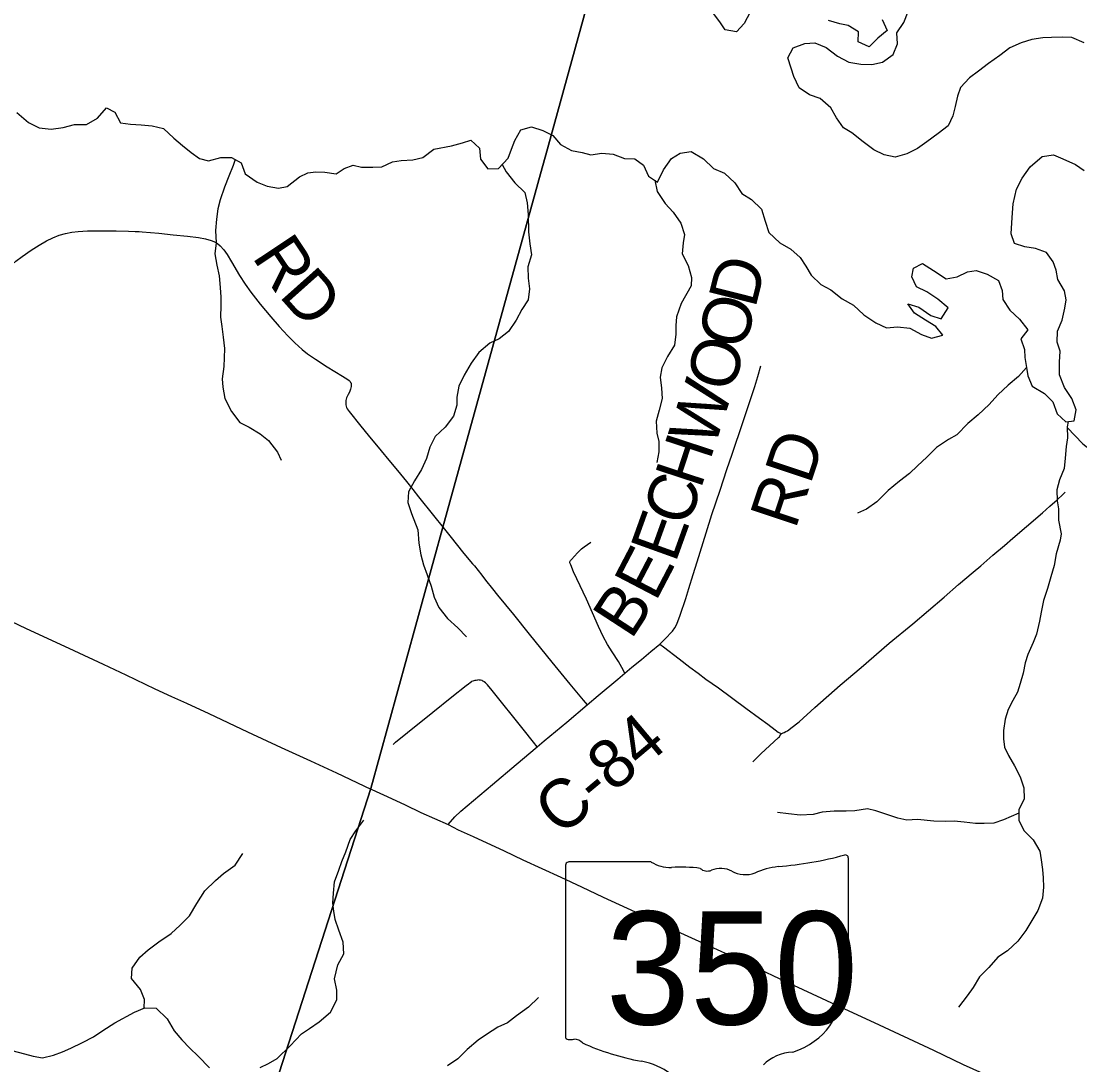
# Model space of a CAD drawing. Extents: x 0 to 34, y 0 to 22.
# Drawn here: x 3.583 to 4.817, y 17.368 to 18.585 of the extents above; entities that cross this region are included whole.
import ezdxf

# ---------------------------------------------------------------- set-up
doc = ezdxf.new("R2010")
doc.units = 0
for name, color, linetype in [('GM_X_County_Road', 7, 'Continuous'), ('GM_X_County_Road_Text', 7, 'Continuous'), ('GM_X_Major_Lake', 7, 'Continuous'), ('GM_X_Minor_River', 7, 'Continuous'), ('GM_X_State_Location', 7, 'Continuous'), ('GM_X_State_Route', 7, 'Continuous'), ('GM_X_State_Shield', 7, 'Continuous'), ('GM_X_Township_Road', 7, 'Continuous'), ('GM_X_Township_Road_Text', 7, 'Continuous')]:
    doc.layers.add(name, color=color, linetype=linetype)

msp = doc.modelspace()

# ---------------------------------------------------------------- linework, layer by layer
at = {"layer": 'GM_X_County_Road'}
for points in [[(4.3273, 17.8584), (4.3332, 17.8639), (4.342, 17.8734), (4.3449, 17.8773), (4.3471, 17.8816), (4.351, 17.892), (4.3575, 17.9114), (4.3611, 17.9233), (4.3661, 17.9393), (4.3709, 17.9541), (4.3813, 17.9879), (4.3881, 18.0093), (4.3975, 18.0376), (4.4054, 18.0619), (4.4118, 18.0799), (4.4241, 18.1166), (4.4381, 18.1587), (4.4417, 18.1703), (4.4451, 18.1829)], [(4.2866, 17.8244), (4.2949, 17.8314), (4.3059, 17.8405), (4.3168, 17.8498), (4.3273, 17.8584)], [(4.2427, 17.7876), (4.2554, 17.7982), (4.2783, 17.8174), (4.2866, 17.8244)], [(4.1843, 17.7384), (4.1926, 17.7454), (4.2188, 17.7674), (4.2427, 17.7876)], [(4.0806, 17.6479), (4.0883, 17.6569), (4.0952, 17.6633), (4.1323, 17.6946), (4.1597, 17.7179), (4.1843, 17.7384)]]:
    msp.add_lwpolyline(points, dxfattribs=at)
at = {"layer": 'GM_X_Major_Lake'}
for points in [[(4.4326, 18.5952), (4.4258, 18.5821), (4.4168, 18.5721), (4.4036, 18.5744), (4.3971, 18.584), (4.3898, 18.5937)], [(4.8218, 18.5594), (4.8075, 18.5658), (4.7962, 18.5661), (4.784, 18.5657), (4.7738, 18.5652), (4.7609, 18.5633), (4.7486, 18.5595), (4.7352, 18.5534), (4.7236, 18.5446), (4.7105, 18.5355), (4.6988, 18.5264), (4.6884, 18.5187), (4.6778, 18.5072), (4.6745, 18.4971), (4.6715, 18.485), (4.6689, 18.4744), (4.6633, 18.4628), (4.6517, 18.4537), (4.6385, 18.4438), (4.6277, 18.4361), (4.6154, 18.43), (4.6016, 18.4262), (4.5888, 18.4289), (4.5769, 18.4345), (4.5643, 18.444), (4.5513, 18.4546), (4.5416, 18.4601), (4.5332, 18.4718), (4.5268, 18.4837), (4.5142, 18.4943), (4.5018, 18.4988), (4.4896, 18.5071), (4.4835, 18.5202), (4.4804, 18.5298), (4.4765, 18.542), (4.4829, 18.5536), (4.4963, 18.5585), (4.5081, 18.5593), (4.5212, 18.554), (4.5345, 18.5438), (4.5476, 18.537), (4.5616, 18.5347), (4.5744, 18.534), (4.587, 18.537), (4.5994, 18.5458), (4.6043, 18.5582), (4.6035, 18.5711), (4.6118, 18.583), (4.6167, 18.5958)], [(4.5865, 18.5867), (4.5922, 18.5737), (4.5814, 18.5649), (4.5712, 18.5549), (4.5585, 18.5606), (4.5588, 18.5723), (4.5469, 18.5795), (4.5371, 18.5817), (4.524, 18.5854)], [(3.5777, 18.4781), (3.5914, 18.4664), (3.6037, 18.4603), (3.6177, 18.4588), (3.6317, 18.4607), (3.6451, 18.4641), (3.6591, 18.4641), (3.6718, 18.4714), (3.6824, 18.4836), (3.6921, 18.4784), (3.6986, 18.4661), (3.7103, 18.4646)], [(3.7103, 18.4646), (3.7227, 18.4639), (3.7356, 18.4628), (3.7487, 18.4594), (3.7609, 18.4484), (3.7709, 18.4398), (3.7809, 18.4315), (3.7906, 18.4244), (3.8011, 18.4219), (3.8156, 18.4256), (3.8281, 18.4257), (3.8393, 18.4193), (3.8438, 18.4066), (3.8579, 18.3968), (3.8696, 18.3923), (3.8828, 18.39), (3.893, 18.392), (3.9074, 18.403), (3.917, 18.4077), (3.9265, 18.4089), (3.9367, 18.4086), (3.9499, 18.4067), (3.9595, 18.4129), (3.9699, 18.4168), (3.9797, 18.4146), (3.9929, 18.4143), (4.0032, 18.4147), (4.0158, 18.4205), (4.0257, 18.4221), (4.0394, 18.4228), (4.0512, 18.4256), (4.064, 18.4354), (4.0846, 18.4394), (4.0972, 18.4429), (4.1071, 18.446), (4.1171, 18.4366), (4.1182, 18.4237), (4.127, 18.4125), (4.1391, 18.4129), (4.1504, 18.4251), (4.1545, 18.4356), (4.1582, 18.4454), (4.1654, 18.4581), (4.1776, 18.4615), (4.1908, 18.4573), (4.2027, 18.4513), (4.2115, 18.4408), (4.2242, 18.4337), (4.237, 18.4314), (4.2468, 18.4289), (4.2597, 18.4308), (4.2729, 18.4297), (4.286, 18.4247), (4.2981, 18.424), (4.3085, 18.4169), (4.3142, 18.4039), (4.3246, 18.3971), (4.3315, 18.4113), (4.341, 18.4247), (4.351, 18.4309), (4.3639, 18.4328), (4.3781, 18.4241), (4.3899, 18.4128), (4.4026, 18.4075), (4.4148, 18.3961), (4.4228, 18.3838), (4.4343, 18.3766), (4.4457, 18.3653), (4.4502, 18.3515), (4.4544, 18.3381), (4.4673, 18.326), (4.48, 18.3188), (4.4911, 18.309), (4.4976, 18.299), (4.5037, 18.2886), (4.5152, 18.2776), (4.5267, 18.2713), (4.5397, 18.261), (4.5531, 18.2534), (4.5653, 18.2421), (4.579, 18.233), (4.5914, 18.227), (4.6043, 18.2281), (4.6186, 18.2266), (4.6324, 18.2194), (4.6441, 18.2149), (4.6571, 18.2187), (4.649, 18.2288), (4.6371, 18.2359), (4.6244, 18.2443), (4.6164, 18.2551), (4.6292, 18.2513), (4.6433, 18.2415), (4.6553, 18.2377), (4.6636, 18.2504), (4.6514, 18.2606), (4.6384, 18.2689), (4.6265, 18.2749), (4.6211, 18.2865), (4.6229, 18.2967), (4.6337, 18.302)], [(4.6337, 18.302), (4.6463, 18.2941), (4.6612, 18.2842), (4.6741, 18.2865), (4.6861, 18.2923), (4.696, 18.2939), (4.7091, 18.2897), (4.7221, 18.2821), (4.7263, 18.2707), (4.7272, 18.26), (4.7352, 18.2476), (4.7466, 18.2371), (4.7565, 18.2247), (4.7482, 18.2143), (4.7524, 18.202), (4.7529, 18.1925), (4.7548, 18.1807), (4.7565, 18.1712), (4.7614, 18.1589), (4.7759, 18.1505), (4.7855, 18.1408), (4.7904, 18.1266), (4.8008, 18.1176), (4.8102, 18.1185), (4.8125, 18.1313), (4.8076, 18.1447), (4.7992, 18.1575), (4.7932, 18.1724), (4.7933, 18.1869), (4.794, 18.1997), (4.7905, 18.2104), (4.7909, 18.2233), (4.7962, 18.2361), (4.7996, 18.25), (4.801, 18.2599), (4.7991, 18.2702), (4.7911, 18.2833), (4.7892, 18.2943), (4.786, 18.3039), (4.778, 18.3151), (4.7653, 18.3197), (4.7528, 18.3215), (4.7408, 18.3253), (4.737, 18.3367), (4.7377, 18.3496), (4.7384, 18.361), (4.7391, 18.3716), (4.743, 18.3886), (4.7498, 18.4016), (4.7589, 18.4147), (4.7729, 18.4268), (4.7862, 18.4287), (4.797, 18.4242), (4.812, 18.4174), (4.822, 18.4106)]]:
    msp.add_lwpolyline(points, dxfattribs=at)
at = {"layer": 'GM_X_Minor_River'}
for points in [[(3.8323, 18.4232), (3.83, 18.4163), (3.8248, 18.4039), (3.82, 18.3911), (3.8148, 18.3764), (3.8123, 18.3658), (3.8105, 18.3537), (3.8095, 18.3405), (3.81, 18.326), (3.8086, 18.3135), (3.811, 18.3002), (3.8137, 18.2876), (3.815, 18.2743), (3.8155, 18.2629), (3.8157, 18.2531), (3.8154, 18.2394), (3.8167, 18.2288), (3.8183, 18.2162), (3.82, 18.2029), (3.8197, 18.1919), (3.8191, 18.1821), (3.8173, 18.1677), (3.8179, 18.1578), (3.8203, 18.1445), (3.8279, 18.1295), (3.8379, 18.1168), (3.8488, 18.1113), (3.8615, 18.1034), (3.8712, 18.0957), (3.8815, 18.0822), (3.8858, 18.0726)], [(4.1436, 18.4177), (4.1481, 18.4089), (4.1584, 18.3961), (4.17, 18.3849), (4.1727, 18.3727), (4.174, 18.3594), (4.1743, 18.3389), (4.1759, 18.3252), (4.1776, 18.3123), (4.1735, 18.2983), (4.174, 18.2851), (4.1756, 18.2725), (4.1738, 18.2596), (4.1664, 18.2484), (4.1597, 18.236), (4.1511, 18.2229), (4.1399, 18.2144), (4.1292, 18.2093), (4.1165, 18.1982), (4.1075, 18.1858), (4.0993, 18.172), (4.093, 18.1592), (4.0908, 18.1463), (4.0906, 18.1368), (4.0869, 18.124), (4.0772, 18.1113), (4.0656, 18.1005), (4.0593, 18.0878), (4.0552, 18.0746), (4.0497, 18.0618), (4.0414, 18.0487), (4.0344, 18.0359), (4.0337, 18.0234), (4.038, 18.0104), (4.0451, 17.9914)], [(4.3215, 18.3992), (4.3242, 18.386), (4.3337, 18.3722), (4.343, 18.3618), (4.3518, 18.3491), (4.3561, 18.3361), (4.3544, 18.3262), (4.3534, 18.3134), (4.3603, 18.2996), (4.3642, 18.2858), (4.364, 18.276), (4.3522, 18.2553), (4.3469, 18.2399), (4.346, 18.2297), (4.3461, 18.2198), (4.3444, 18.2069), (4.3361, 18.1938), (4.3298, 18.1803), (4.3277, 18.1697), (4.3293, 18.1568), (4.3302, 18.1446), (4.3265, 18.131), (4.3232, 18.1182), (4.3237, 18.1042), (4.3261, 18.0946), (4.3263, 18.0825), (4.3237, 18.07)], [(4.7548, 18.1809), (4.7456, 18.1705), (4.7332, 18.1602), (4.7213, 18.149), (4.7112, 18.1375), (4.6984, 18.1256), (4.6865, 18.1156), (4.6737, 18.1022), (4.6637, 18.0967), (4.6499, 18.0874), (4.6387, 18.0763), (4.6279, 18.0663), (4.6182, 18.0573), (4.6067, 18.0481), (4.5936, 18.0373), (4.5804, 18.0243), (4.5681, 18.0158), (4.5578, 18.0111)], [(4.8033, 18.1178), (4.8023, 18.1117), (4.8024, 18.0988), (4.8011, 18.0886), (4.7997, 18.075), (4.7987, 18.0629), (4.7931, 18.0497), (4.7902, 18.038), (4.7907, 18.0255), (4.792, 18.016), (4.7921, 18.0027), (4.795, 17.9869), (4.7941, 17.9795)], [(4.8023, 18.111), (4.8205, 18.092), (4.8324, 18.0823), (4.8433, 18.0768), (4.8534, 18.0724), (4.8654, 18.0669), (4.8759, 18.0602), (4.8806, 18.0476), (4.8804, 18.0377), (4.8809, 18.0256), (4.8924, 18.017), (4.8949, 18.0056), (4.8969, 17.9926), (4.9154, 17.9775)], [(4.0451, 17.9914), (4.0463, 17.9758), (4.0488, 17.9625), (4.052, 17.9507), (4.056, 17.9389), (4.0608, 17.9259), (4.0644, 17.9129), (4.0699, 17.9011), (4.0799, 17.8881), (4.0919, 17.8773), (4.102, 17.8669)], [(4.7941, 17.9795), (4.7893, 17.9634), (4.7869, 17.9498), (4.7833, 17.9366), (4.7793, 17.9233), (4.7745, 17.9093), (4.7717, 17.8957), (4.77, 17.8851), (4.7664, 17.87), (4.7624, 17.8602), (4.7565, 17.8462), (4.7534, 17.8364), (4.7509, 17.8242), (4.7473, 17.8125), (4.7441, 17.8023), (4.7387, 17.7925), (4.7332, 17.782), (4.73, 17.7706), (4.7279, 17.7574), (4.7278, 17.7479), (4.7292, 17.738), (4.7336, 17.7284), (4.7406, 17.7162), (4.7473, 17.7036), (4.7516, 17.6906), (4.7522, 17.6777), (4.7459, 17.6649), (4.7458, 17.6527), (4.752, 17.6405), (4.7625, 17.6301), (4.7703, 17.6167), (4.772, 17.6068), (4.7734, 17.5954), (4.774, 17.5859), (4.7746, 17.5749), (4.7736, 17.562), (4.7681, 17.5476), (4.7623, 17.5378), (4.7541, 17.5243), (4.7448, 17.5119), (4.7325, 17.5007), (4.7214, 17.4932), (4.7107, 17.4812), (4.6999, 17.4704), (4.6925, 17.4579), (4.6855, 17.4482), (4.6755, 17.435)], [(4.7459, 17.6611), (4.7279, 17.6533), (4.7165, 17.6493), (4.7055, 17.6491), (4.6953, 17.6492), (4.682, 17.6506), (4.6703, 17.6519), (4.6608, 17.6516), (4.6468, 17.6518), (4.6278, 17.6536), (4.6153, 17.653), (4.6047, 17.6554), (4.5919, 17.6594), (4.5791, 17.6637), (4.5693, 17.6661), (4.5548, 17.6637), (4.5446, 17.6634), (4.5305, 17.6636), (4.5165, 17.6623), (4.5062, 17.6594), (4.491, 17.6589), (4.4774, 17.6602), (4.4645, 17.6619)], [(3.8615, 17.3645), (3.8711, 17.3693), (3.8814, 17.3752), (3.8964, 17.3898), (3.9095, 17.4037), (3.919, 17.41), (3.9302, 17.4178), (3.9436, 17.429), (3.951, 17.4434), (3.9508, 17.4548), (3.948, 17.4681), (3.952, 17.4844), (3.959, 17.4972), (3.9581, 17.5108), (3.9533, 17.5246), (3.949, 17.5372), (3.9472, 17.5467), (3.9462, 17.5562), (3.9468, 17.5679), (3.9481, 17.5812), (3.9532, 17.5948), (3.9568, 17.6046), (3.9615, 17.616), (3.9662, 17.6303), (3.9728, 17.6405), (3.9825, 17.6529)], [(3.7262, 17.4339), (3.7265, 17.4438), (3.7218, 17.4556), (3.7114, 17.4683), (3.7123, 17.4804), (3.7212, 17.4932), (3.7308, 17.5018), (3.7434, 17.5111), (3.7576, 17.5208), (3.7684, 17.5305), (3.7792, 17.5414), (3.7877, 17.5557), (3.797, 17.5707), (3.8093, 17.5827), (3.8189, 17.5909), (3.8323, 17.6006), (3.8413, 17.6142)], [(4.1861, 17.4462), (4.1742, 17.435), (4.1604, 17.425), (4.1497, 17.4167), (4.1386, 17.4116), (4.1252, 17.403), (4.1156, 17.3963), (4.1026, 17.3855), (4.0918, 17.3746), (4.0799, 17.3664)], [(3.6779, 17.4076), (3.692, 17.4165), (3.715, 17.4291), (3.7272, 17.4343), (3.7404, 17.4337), (3.7531, 17.4214), (3.7613, 17.4072), (3.7702, 17.3969), (3.7796, 17.3872), (3.7893, 17.3776), (3.8024, 17.3642)], [(3.5721, 17.3844), (3.5868, 17.3804), (3.5967, 17.3776), (3.6076, 17.3759), (3.6206, 17.3788), (3.6309, 17.3828), (3.6408, 17.3872), (3.6545, 17.3939), (3.6671, 17.4005), (3.6779, 17.4076)]]:
    msp.add_lwpolyline(points, dxfattribs=at)
at = {"layer": 'GM_X_State_Route'}
for points in [[(3.5517, 17.894), (3.5889, 17.8766), (3.6182, 17.863), (3.6441, 17.8508), (3.6783, 17.8347), (3.7048, 17.8224), (3.7385, 17.8063), (3.7582, 17.7973), (3.7757, 17.7893), (3.8017, 17.7773), (3.8467, 17.7561), (3.8861, 17.7377), (3.92, 17.7222), (3.9504, 17.708), (3.9905, 17.6893)], [(3.9905, 17.6893), (3.9915, 17.6889), (4.0146, 17.6781), (4.0304, 17.6709), (4.0489, 17.6621), (4.0806, 17.6479), (4.0923, 17.6419), (4.1098, 17.6338), (4.1459, 17.6172), (4.1678, 17.6069), (4.2118, 17.5864), (4.236, 17.5751), (4.2613, 17.5633), (4.3172, 17.5375), (4.3516, 17.5217), (4.3815, 17.508), (4.4205, 17.49), (4.4666, 17.4684), (4.5325, 17.4377), (4.577, 17.4169), (4.6463, 17.3846), (4.6811, 17.3682), (4.7112, 17.3543)]]:
    msp.add_lwpolyline(points, dxfattribs=at)
at = {"layer": 'GM_X_State_Shield'}
for p, q in [((4.2175, 17.6007), (4.2175, 17.4006)), ((4.3173, 17.6042), (4.2207, 17.6042)), ((4.5471, 17.5044), (4.5471, 17.6091)), ((4.547, 17.5045), (4.5471, 17.5044))]:
    msp.add_line(p, q, dxfattribs=at)
for centre, major_axis, start_param, end_param in [((4.4297, 17.877), (0.3495, 0), 4.814394, 5.042369), ((4.5434, 17.6095), (0.00367, 0), 6.141152, 7.989035), ((4.2213, 17.6011), (0.00382, 0), 1.712693, 3.28349), ((4.3402, 17.6274), (0.037, 0), 4.042523, 4.731795), ((4.3525, 17.4918), (0.133, 0), 1.404758, 1.657858), ((4.3984, 17.579), (0.0222, 0), 0.950623, 2.079405), ((4.4742, 17.543), (0.0703, 0), 1.699011, 2.107814), ((4.3827, 17.6022), (0.0107, 0), 3.836095, 5.185415), ((4.4271, 17.6108), (0.0267, 0), 4.081561, 5.145723), ((4.5462, 17.4967), (0.00568, 0), 1.883978, 3.671073), ((4.5432, 17.504), (0.00393, 0), 5.05454, 6.418171), ((4.5101, 17.4835), (0.0341, 0), 5.934695, 6.695948), ((4.5602, 17.4606), (0.0248, 0), 2.387724, 3.262537), ((4.4492, 17.4473), (0.0874, 0), 5.101752, 6.440018), ((4.2213, 17.4001), (0.00385, 0), 3.00124, 4.508301), ((4.2219, 17.4206), (0.0294, 0), 4.665946, 4.897461), ((4.2279, 17.389), (0.0106, 0), 0.519207, 1.627899), ((4.3617, 17.5688), (0.2524, 0), 4.195997, 4.488961), ((4.4861, 17.3444), (0.0479, 0), 1.647645, 2.488434), ((4.2865, 17.3107), (0.079, 0), 0.823519, 1.323587)]:
    msp.add_ellipse(centre, major_axis=major_axis, ratio=0.8, start_param=start_param, end_param=end_param, dxfattribs=at)
at = {"layer": 'GM_X_Township_Road'}
for points in [[(3.7787, 17.0143), (3.7921, 17.074), (3.9903, 17.6899), (4.0744, 17.9948), (4.1901, 18.4135), (4.1943, 18.4289), (4.2897, 18.7747), (4.3389, 18.9527), (4.4789, 19.5742), (4.4849, 19.6021), (4.4654, 19.6041), (3.501, 19.6889), (3.4805, 19.8366), (3.1735, 19.8394), (3.1019, 19.912), (2.3144, 20.5665), (2.1, 20.7431), (2.1, 15.597), (2.2517, 15.5643), (3.1228, 15.3686), (3.3385, 15.3189), (3.6691, 16.5264), (3.7277, 16.7873)], [(8.9, 16.5763), (8.9, 19.1426), (8.4186, 19.1875), (7.8888, 19.2268), (7.1834, 19.2978), (6.3561, 19.3959), (5.8809, 19.4409), (5.6889, 19.4592), (5.1411, 19.5203), (4.4849, 19.6021), (4.4789, 19.5742), (4.3389, 18.9527), (4.2897, 18.7747), (4.1943, 18.4289), (4.1901, 18.4135), (4.0744, 17.9948), (3.9903, 17.6899), (3.7921, 17.074)], [(3.4721, 18.2124), (3.486, 18.2243), (3.5131, 18.2481), (3.529, 18.262), (3.539, 18.2702), (3.5437, 18.2742), (3.55, 18.2801), (3.5652, 18.2944), (3.5766, 18.3047), (3.5839, 18.3104), (3.5945, 18.3177), (3.604, 18.3235), (3.6126, 18.3284), (3.6198, 18.332), (3.6271, 18.335), (3.6347, 18.3372), (3.6419, 18.3386), (3.6492, 18.3394), (3.6603, 18.34), (3.6808, 18.3402), (3.6894, 18.3402), (3.6938, 18.3401), (3.708, 18.3398), (3.7156, 18.3395)], [(3.7156, 18.3395), (3.7203, 18.3393), (3.7238, 18.339), (3.7433, 18.3373), (3.7599, 18.3356), (3.7766, 18.3339), (3.7895, 18.3323), (3.7979, 18.3307), (3.8044, 18.3289), (3.8095, 18.3268), (3.8119, 18.3253), (3.8149, 18.3225), (3.819, 18.318), (3.823, 18.3125), (3.8281, 18.3041), (3.8375, 18.2881), (3.8438, 18.2781), (3.8507, 18.2685), (3.8614, 18.2548), (3.8738, 18.24), (3.8835, 18.2288), (3.8936, 18.2178), (3.902, 18.2094), (3.9104, 18.202), (3.9168, 18.1969), (3.926, 18.1904), (3.9395, 18.1816), (3.9576, 18.1708), (3.9638, 18.1667), (3.9653, 18.1655), (3.9665, 18.1644), (3.9669, 18.1634), (3.9674, 18.1624), (3.9677, 18.1607)], [(3.9677, 18.1607), (3.9674, 18.1585), (3.9667, 18.1557), (3.9655, 18.1522), (3.9641, 18.1494), (3.9623, 18.1454), (3.9615, 18.1422), (3.9613, 18.1389), (3.9615, 18.1373), (3.9623, 18.1342), (3.963, 18.1326), (3.9651, 18.1294), (3.9788, 18.1125), (3.9875, 18.1019), (4.0024, 18.0836), (4.0116, 18.0727), (4.0215, 18.0607), (4.032, 18.0477), (4.0396, 18.0384), (4.0462, 18.0299), (4.0635, 18.0082), (4.0747, 17.9943)], [(4.7015, 17.9497), (4.7156, 17.9618), (4.7292, 17.9734), (4.7388, 17.9817), (4.7546, 17.9953), (4.7733, 18.0115), (4.7819, 18.019), (4.7906, 18.0265), (4.7972, 18.0327), (4.8, 18.0355)], [(4.0747, 17.9943), (4.0824, 17.9847), (4.099, 17.964), (4.109, 17.9519), (4.1112, 17.9494), (4.1199, 17.9386), (4.1243, 17.9328), (4.1324, 17.9227), (4.1382, 17.9154), (4.1566, 17.8927), (4.1749, 17.87), (4.2016, 17.8372), (4.2223, 17.8117), (4.238, 17.7931), (4.2427, 17.7876)], [(4.2224, 17.9542), (4.2233, 17.9556), (4.2238, 17.9561), (4.2244, 17.9569), (4.2278, 17.9608), (4.2315, 17.9648), (4.2361, 17.9693), (4.2393, 17.9719), (4.243, 17.9745), (4.2471, 17.9773)], [(4.2866, 17.8244), (4.283, 17.8309), (4.279, 17.8379), (4.2716, 17.8494), (4.2663, 17.8578), (4.2613, 17.8671), (4.2558, 17.879), (4.2419, 17.9108), (4.2305, 17.9345), (4.2269, 17.9427), (4.2236, 17.9506), (4.2232, 17.9515), (4.2229, 17.9522), (4.2226, 17.9532), (4.2224, 17.9542)], [(4.4691, 17.7539), (4.4723, 17.7551), (4.4744, 17.7562), (4.476, 17.757), (4.4777, 17.7582), (4.4801, 17.7601), (4.4896, 17.7678), (4.508, 17.7845), (4.5376, 17.8103), (4.5621, 17.8309), (4.5948, 17.8593), (4.6224, 17.8819), (4.6587, 17.9131), (4.6756, 17.9278), (4.6926, 17.9421), (4.7015, 17.9497)], [(4.3273, 17.8584), (4.3316, 17.8551), (4.3498, 17.8411), (4.3625, 17.8314), (4.3721, 17.8243), (4.3809, 17.8175), (4.3956, 17.8072), (4.4277, 17.7836), (4.4434, 17.7721), (4.4534, 17.7648), (4.4616, 17.7582), (4.4653, 17.7556), (4.4669, 17.7549), (4.4691, 17.7539)], [(4.0165, 17.7414), (4.0193, 17.7438), (4.0334, 17.7551), (4.0629, 17.7788), (4.085, 17.7969), (4.1015, 17.8101), (4.1042, 17.8121), (4.1063, 17.8136), (4.1077, 17.8145), (4.1084, 17.8149), (4.1096, 17.8155), (4.1109, 17.816), (4.112, 17.8162), (4.1133, 17.8164), (4.1152, 17.8165)], [(4.1843, 17.7384), (4.18, 17.7439), (4.1679, 17.7589), (4.1318, 17.804), (4.1263, 17.8108), (4.124, 17.8131), (4.1227, 17.8142), (4.1221, 17.8146), (4.1211, 17.8152), (4.1202, 17.8157), (4.1185, 17.8162), (4.1167, 17.8164), (4.1152, 17.8165)], [(4.4359, 17.721), (4.4451, 17.7302), (4.4657, 17.7492), (4.4667, 17.7503), (4.4674, 17.7512), (4.4684, 17.7527), (4.4691, 17.7539)]]:
    msp.add_lwpolyline(points, dxfattribs=at)

# ---------------------------------------------------------------- texts
at = {"layer": 'GM_X_County_Road_Text'}
for s, height, rotation, p in [('D', 0.0568, 75.879, (4.4385, 18.2487)), ('O', 0.0568, 75.653, (4.426, 18.2)), ('O', 0.0568, 73.7336, (4.4115, 18.15)), ('W', 0.0568, 71.9832, (4.3906, 18.0856)), ('RD', 0.05682, 71.5653, (4.4853, 17.9911)), ('H', 0.0568, 71.8565, (4.3749, 18.038)), ('C', 0.0568, 71.8744, (4.3604, 17.9936)), ('E', 0.0568, 70.1861, (4.3454, 17.9519)), ('E', 0.0568, 62.4246, (4.3224, 17.9066)), ('B', 0.0568, 56.947, (4.2939, 17.8623)), ('C-84', 0.05682, 39.9785, (4.2119, 17.6327))]:
    msp.add_text(s, height=height, rotation=rotation, dxfattribs=at).set_placement(p)
at = {"layer": 'GM_X_State_Location'}
for s in ['s', 'r']:
    msp.add_text(s, height=0.000189, dxfattribs=at).set_placement((4.3786, 17.4873))
msp.add_text('350', height=0.000189, rotation=0, dxfattribs=at).set_placement((4.3117, 17.4736))
at = {"layer": 'GM_X_State_Shield'}
msp.add_text('350', height=0.13184, dxfattribs=at).set_placement((4.2644, 17.4147))
at = {"layer": 'GM_X_Township_Road_Text'}
for s, rotation, p in [('R', 303.6083, (3.8512, 18.31)), ('D', 311.7166, (3.8823, 18.2643))]:
    msp.add_text(s, height=0.0568, rotation=rotation, dxfattribs=at).set_placement(p)

doc.saveas('drawing.dxf')
